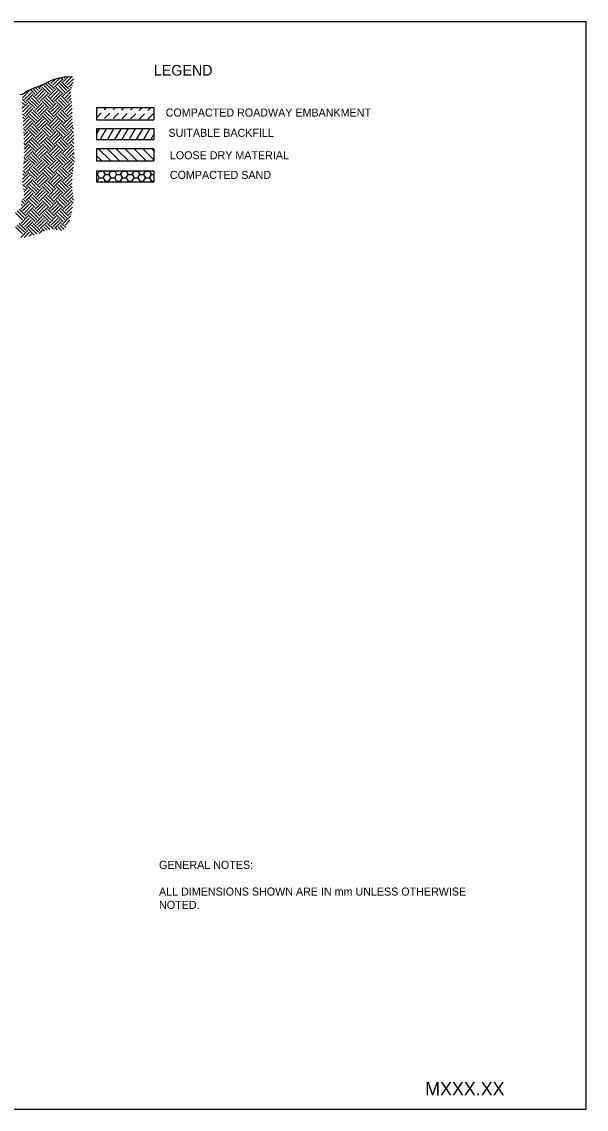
# Model space of a CAD drawing. Extents: x -439.1 to -407.9, y -458.1 to -436.2.
# Drawn here: x -418.43 to -407.86, y -458.05 to -437.68 of the extents above; entities that cross this region are included whole.
import ezdxf

# ---------------------------------------------------------------- set-up
doc = ezdxf.new("R2010")
doc.units = 0
for name, color, linetype in [('Bridge-Named Boundary', 7, 'Continuous'), ('Level 4', 7, 'Continuous'), ('Level 46', 7, 'Continuous')]:
    doc.layers.add(name, color=color, linetype=linetype)

msp = doc.modelspace()

# ---------------------------------------------------------------- linework, layer by layer
at = {"layer": 'Bridge-Named Boundary'}
msp.add_lwpolyline([(-439.109, -458.051), (-407.859, -458.051), (-407.859, -437.676), (-439.109, -437.676)], close=True, dxfattribs=at)
at = {"layer": 'Level 4'}
for p, q in [((-418.083, -438.901), (-418.035, -438.853)), ((-417.884, -439), (-418.016, -438.867)), ((-417.851, -438.967), (-417.983, -438.834)), ((-417.818, -438.934), (-417.94, -438.811)), ((-417.884, -438.834), (-417.805, -438.756)), ((-417.851, -438.867), (-417.718, -438.735)), ((-417.818, -438.901), (-417.685, -438.768)), ((-417.619, -439), (-417.751, -438.867)), ((-417.586, -438.967), (-417.718, -438.834)), ((-417.652, -438.768), (-417.688, -438.732)), ((-417.552, -438.934), (-417.685, -438.801)), ((-417.652, -438.801), (-417.559, -438.708)), ((-417.619, -438.735), (-417.627, -438.727)), ((-417.619, -438.834), (-417.493, -438.709)), ((-417.586, -438.867), (-417.462, -438.744)), ((-417.552, -438.901), (-417.469, -438.817)), ((-417.484, -438.87), (-417.486, -438.867)), ((-418.414, -439.099), (-418.282, -438.967)), ((-418.381, -439.133), (-418.248, -439)), ((-418.348, -439.166), (-418.215, -439.033)), ((-418.182, -439.033), (-418.269, -438.947)), ((-418.149, -439), (-418.222, -438.927)), ((-418.083, -439.199), (-418.215, -439.066)), ((-418.182, -439.066), (-418.05, -438.934)), ((-418.116, -438.967), (-418.172, -438.911)), ((-418.149, -439.099), (-418.016, -438.967)), ((-418.083, -438.934), (-418.124, -438.892)), ((-418.116, -439.133), (-417.983, -439)), ((-418.083, -439.166), (-417.95, -439.033)), ((-417.917, -439.033), (-418.05, -438.901)), ((-417.818, -439.199), (-417.95, -439.066)), ((-417.917, -439.066), (-417.784, -438.934)), ((-417.884, -439.099), (-417.751, -438.967)), ((-417.851, -439.133), (-417.718, -439)), ((-417.818, -439.166), (-417.685, -439.033)), ((-417.652, -439.033), (-417.784, -438.901)), ((-417.552, -439.199), (-417.685, -439.066)), ((-417.652, -439.066), (-417.519, -438.934)), ((-417.619, -439.099), (-417.509, -438.99)), ((-417.586, -439.133), (-417.511, -439.058)), ((-417.498, -438.922), (-417.519, -438.901)), ((-418.381, -439.232), (-418.423, -439.19)), ((-418.414, -439.265), (-418.423, -439.257)), ((-418.42, -439.304), (-418.315, -439.199)), ((-418.348, -439.199), (-418.419, -439.128)), ((-418.414, -439.365), (-418.282, -439.232)), ((-418.381, -439.398), (-418.248, -439.265)), ((-418.182, -439.298), (-418.315, -439.166)), ((-418.149, -439.265), (-418.282, -439.133)), ((-418.116, -439.232), (-418.248, -439.099)), ((-418.182, -439.332), (-418.05, -439.199)), ((-418.149, -439.365), (-418.016, -439.232)), ((-418.116, -439.398), (-417.983, -439.265)), ((-417.917, -439.298), (-418.05, -439.166)), ((-417.884, -439.265), (-418.016, -439.133)), ((-417.851, -439.232), (-417.983, -439.099)), ((-417.917, -439.332), (-417.784, -439.199)), ((-417.884, -439.365), (-417.751, -439.232)), ((-417.851, -439.398), (-417.718, -439.265)), ((-417.652, -439.298), (-417.784, -439.166)), ((-417.619, -439.265), (-417.751, -439.133)), ((-417.586, -439.232), (-417.718, -439.099)), ((-417.652, -439.332), (-417.519, -439.199)), ((-417.619, -439.365), (-417.491, -439.237)), ((-417.552, -439.166), (-417.503, -439.116)), ((-417.494, -439.191), (-417.519, -439.166)), ((-417.032, -439.283), (-415.957, -439.283)), ((-417.032, -439.283), (-417.032, -439.515)), ((-417.032, -439.308), (-417.007, -439.283)), ((-416.883, -439.325), (-416.841, -439.283)), ((-416.72, -439.328), (-416.676, -439.283)), ((-416.558, -439.332), (-416.51, -439.283)), ((-416.396, -439.335), (-416.344, -439.283)), ((-416.233, -439.338), (-416.178, -439.283)), ((-416.071, -439.341), (-416.013, -439.283)), ((-415.957, -439.283), (-415.957, -439.515)), ((-418.348, -439.464), (-418.414, -439.398)), ((-418.381, -439.497), (-418.409, -439.469)), ((-418.404, -439.553), (-418.315, -439.464)), ((-418.348, -439.431), (-418.215, -439.298)), ((-418.182, -439.564), (-418.315, -439.431)), ((-418.149, -439.53), (-418.282, -439.398)), ((-418.116, -439.497), (-418.248, -439.365)), ((-418.083, -439.464), (-418.215, -439.332)), ((-418.182, -439.597), (-418.05, -439.464)), ((-418.083, -439.431), (-417.95, -439.298)), ((-417.917, -439.564), (-418.05, -439.431)), ((-417.884, -439.53), (-418.016, -439.398)), ((-417.851, -439.497), (-417.983, -439.365)), ((-417.818, -439.464), (-417.95, -439.332)), ((-417.917, -439.597), (-417.784, -439.464)), ((-417.818, -439.431), (-417.685, -439.298)), ((-417.652, -439.564), (-417.784, -439.431)), ((-417.619, -439.53), (-417.751, -439.398)), ((-417.586, -439.497), (-417.718, -439.365)), ((-417.552, -439.464), (-417.685, -439.332)), ((-417.652, -439.597), (-417.519, -439.464)), ((-417.586, -439.398), (-417.489, -439.301)), ((-417.552, -439.431), (-417.488, -439.367)), ((-417.485, -439.466), (-417.519, -439.431)), ((-417.032, -439.474), (-416.943, -439.385)), ((-416.88, -439.487), (-416.78, -439.388)), ((-416.717, -439.491), (-416.618, -439.391)), ((-416.555, -439.494), (-416.455, -439.394)), ((-416.392, -439.497), (-416.293, -439.398)), ((-416.23, -439.501), (-416.13, -439.401)), ((-416.067, -439.504), (-415.968, -439.404)), ((-418.401, -439.617), (-418.282, -439.497)), ((-418.348, -439.729), (-418.399, -439.678)), ((-418.381, -439.663), (-418.248, -439.53)), ((-418.348, -439.696), (-418.215, -439.564)), ((-418.149, -439.796), (-418.282, -439.663)), ((-418.116, -439.762), (-418.248, -439.63)), ((-418.083, -439.729), (-418.215, -439.597)), ((-418.149, -439.63), (-418.016, -439.497)), ((-418.116, -439.663), (-417.983, -439.53)), ((-418.083, -439.696), (-417.95, -439.564)), ((-417.884, -439.796), (-418.016, -439.663)), ((-417.851, -439.762), (-417.983, -439.63)), ((-417.818, -439.729), (-417.95, -439.597)), ((-417.884, -439.63), (-417.751, -439.497)), ((-417.851, -439.663), (-417.718, -439.53)), ((-417.818, -439.696), (-417.685, -439.564)), ((-417.619, -439.796), (-417.751, -439.663)), ((-417.586, -439.762), (-417.718, -439.63)), ((-417.552, -439.729), (-417.685, -439.597)), ((-417.619, -439.63), (-417.486, -439.497)), ((-417.586, -439.663), (-417.477, -439.555)), ((-417.552, -439.696), (-417.471, -439.615)), ((-417.464, -439.685), (-417.486, -439.663)), ((-417.032, -439.515), (-415.957, -439.515)), ((-417.032, -439.674), (-415.957, -439.674)), ((-417.032, -439.674), (-417.032, -439.882)), ((-416.977, -439.674), (-417.032, -439.768)), ((-416.842, -439.674), (-416.962, -439.881)), ((-416.707, -439.674), (-416.826, -439.881)), ((-416.571, -439.674), (-416.691, -439.881)), ((-416.436, -439.674), (-416.556, -439.881)), ((-416.301, -439.674), (-416.42, -439.881)), ((-416.165, -439.674), (-416.285, -439.881)), ((-416.03, -439.674), (-416.15, -439.881)), ((-415.957, -439.674), (-415.957, -439.882)), ((-418.381, -439.762), (-418.397, -439.747)), ((-418.394, -439.809), (-418.315, -439.729)), ((-418.392, -439.873), (-418.282, -439.762)), ((-418.381, -439.928), (-418.248, -439.796)), ((-418.348, -439.961), (-418.215, -439.829)), ((-418.182, -439.829), (-418.315, -439.696)), ((-418.116, -440.028), (-418.248, -439.895)), ((-418.083, -439.994), (-418.215, -439.862)), ((-418.182, -439.862), (-418.05, -439.729)), ((-418.149, -439.895), (-418.016, -439.762)), ((-418.116, -439.928), (-417.983, -439.796)), ((-418.083, -439.961), (-417.95, -439.829)), ((-417.917, -439.829), (-418.05, -439.696)), ((-417.851, -440.028), (-417.983, -439.895)), ((-417.818, -439.994), (-417.95, -439.862)), ((-417.917, -439.862), (-417.784, -439.729)), ((-417.884, -439.895), (-417.751, -439.762)), ((-417.851, -439.928), (-417.718, -439.796)), ((-417.818, -439.961), (-417.685, -439.829)), ((-417.652, -439.829), (-417.784, -439.696)), ((-417.586, -440.028), (-417.718, -439.895)), ((-417.552, -439.994), (-417.685, -439.862)), ((-417.652, -439.862), (-417.519, -439.729)), ((-417.619, -439.895), (-417.486, -439.762)), ((-417.586, -439.928), (-417.456, -439.798)), ((-417.552, -439.961), (-417.455, -439.863)), ((-417.458, -439.757), (-417.519, -439.696)), ((-417.032, -439.882), (-415.957, -439.882)), ((-415.958, -439.783), (-416.015, -439.881)), ((-418.348, -439.994), (-418.389, -439.954)), ((-418.381, -440.028), (-418.386, -440.022)), ((-418.385, -440.064), (-418.315, -439.994)), ((-418.383, -440.129), (-418.282, -440.028)), ((-418.381, -440.193), (-418.248, -440.061)), ((-418.348, -440.226), (-418.215, -440.094)), ((-418.182, -440.094), (-418.315, -439.961)), ((-418.149, -440.061), (-418.282, -439.928)), ((-418.182, -440.127), (-418.05, -439.994)), ((-418.149, -440.16), (-418.016, -440.028)), ((-418.116, -440.193), (-417.983, -440.061)), ((-418.083, -440.226), (-417.95, -440.094)), ((-417.917, -440.094), (-418.05, -439.961)), ((-417.884, -440.061), (-418.016, -439.928)), ((-417.917, -440.127), (-417.784, -439.994)), ((-417.884, -440.16), (-417.751, -440.028)), ((-417.851, -440.193), (-417.718, -440.061)), ((-417.818, -440.226), (-417.685, -440.094)), ((-417.652, -440.094), (-417.784, -439.961)), ((-417.619, -440.061), (-417.751, -439.928)), ((-417.652, -440.127), (-417.519, -439.994)), ((-417.619, -440.16), (-417.486, -440.028)), ((-417.586, -440.193), (-417.453, -440.061)), ((-417.455, -440.026), (-417.519, -439.961)), ((-417.455, -439.959), (-417.486, -439.928)), ((-417.032, -440.053), (-415.957, -440.053)), ((-417.032, -440.053), (-417.032, -440.284)), ((-416.997, -440.052), (-416.765, -440.284)), ((-416.832, -440.052), (-416.6, -440.284)), ((-416.666, -440.052), (-416.434, -440.284)), ((-416.5, -440.052), (-416.268, -440.284)), ((-416.334, -440.052), (-416.102, -440.284)), ((-416.169, -440.052), (-415.958, -440.263)), ((-416.003, -440.052), (-415.958, -440.098)), ((-415.957, -440.053), (-415.957, -440.284)), ((-418.399, -440.41), (-418.282, -440.293)), ((-418.395, -440.34), (-418.315, -440.26)), ((-418.381, -440.293), (-418.392, -440.282)), ((-418.348, -440.26), (-418.388, -440.22)), ((-418.182, -440.359), (-418.315, -440.226)), ((-418.149, -440.326), (-418.282, -440.193)), ((-418.116, -440.293), (-418.248, -440.16)), ((-418.083, -440.26), (-418.215, -440.127)), ((-418.182, -440.392), (-418.05, -440.26)), ((-418.149, -440.425), (-418.016, -440.293)), ((-417.917, -440.359), (-418.05, -440.226)), ((-417.884, -440.326), (-418.016, -440.193)), ((-417.851, -440.293), (-417.983, -440.16)), ((-417.818, -440.26), (-417.95, -440.127)), ((-417.917, -440.392), (-417.784, -440.26)), ((-417.884, -440.425), (-417.751, -440.293)), ((-417.652, -440.359), (-417.784, -440.226)), ((-417.619, -440.326), (-417.751, -440.193)), ((-417.586, -440.293), (-417.718, -440.16)), ((-417.552, -440.26), (-417.685, -440.127)), ((-417.652, -440.392), (-417.519, -440.26)), ((-417.619, -440.425), (-417.486, -440.293)), ((-417.552, -440.226), (-417.45, -440.124)), ((-417.445, -440.3), (-417.519, -440.226)), ((-417.444, -440.236), (-417.486, -440.193)), ((-417.447, -440.166), (-417.453, -440.16)), ((-417.032, -440.184), (-416.931, -440.284)), ((-417.032, -440.284), (-415.957, -440.284)), ((-418.348, -440.525), (-418.402, -440.47)), ((-418.381, -440.458), (-418.248, -440.326)), ((-418.348, -440.492), (-418.215, -440.359)), ((-418.182, -440.624), (-418.315, -440.492)), ((-418.149, -440.591), (-418.282, -440.458)), ((-418.116, -440.558), (-418.248, -440.425)), ((-418.083, -440.525), (-418.215, -440.392)), ((-418.116, -440.458), (-417.983, -440.326)), ((-418.083, -440.492), (-417.95, -440.359)), ((-417.917, -440.624), (-418.05, -440.492)), ((-417.884, -440.591), (-418.016, -440.458)), ((-417.851, -440.558), (-417.983, -440.425)), ((-417.818, -440.525), (-417.95, -440.392)), ((-417.851, -440.458), (-417.718, -440.326)), ((-417.818, -440.492), (-417.685, -440.359)), ((-417.652, -440.624), (-417.784, -440.492)), ((-417.619, -440.591), (-417.751, -440.458)), ((-417.586, -440.558), (-417.718, -440.425)), ((-417.552, -440.525), (-417.685, -440.392)), ((-417.586, -440.458), (-417.453, -440.326)), ((-417.552, -440.492), (-417.459, -440.399)), ((-417.478, -440.533), (-417.519, -440.492)), ((-417.47, -440.474), (-417.486, -440.458)), ((-417.032, -440.468), (-417.032, -440.675)), ((-417.032, -440.468), (-415.957, -440.468)), ((-417.014, -440.54), (-416.978, -440.478)), ((-416.984, -440.467), (-416.978, -440.478)), ((-416.978, -440.478), (-416.905, -440.478)), ((-416.905, -440.478), (-416.899, -440.467)), ((-416.905, -440.478), (-416.869, -440.54)), ((-416.797, -440.54), (-416.761, -440.478)), ((-416.767, -440.467), (-416.761, -440.478)), ((-416.761, -440.478), (-416.689, -440.478)), ((-416.689, -440.478), (-416.683, -440.467)), ((-416.689, -440.478), (-416.653, -440.54)), ((-416.581, -440.54), (-416.545, -440.478)), ((-416.551, -440.467), (-416.545, -440.478)), ((-416.545, -440.478), (-416.472, -440.478)), ((-416.472, -440.478), (-416.466, -440.467)), ((-416.472, -440.478), (-416.436, -440.54)), ((-416.364, -440.54), (-416.328, -440.478)), ((-416.334, -440.467), (-416.328, -440.478)), ((-416.328, -440.478), (-416.256, -440.478)), ((-416.256, -440.478), (-416.25, -440.467)), ((-416.256, -440.478), (-416.22, -440.54)), ((-416.148, -440.54), (-416.112, -440.478)), ((-416.118, -440.467), (-416.112, -440.478)), ((-416.112, -440.478), (-416.039, -440.478)), ((-416.039, -440.478), (-416.033, -440.467)), ((-416.039, -440.478), (-416.003, -440.54)), ((-415.957, -440.468), (-415.957, -440.675)), ((-418.415, -440.625), (-418.315, -440.525)), ((-418.414, -440.69), (-418.282, -440.558)), ((-418.381, -440.558), (-418.408, -440.531)), ((-418.381, -440.724), (-418.248, -440.591)), ((-418.348, -440.757), (-418.215, -440.624)), ((-418.116, -440.823), (-418.248, -440.69)), ((-418.083, -440.79), (-418.215, -440.657)), ((-418.182, -440.657), (-418.05, -440.525)), ((-418.149, -440.69), (-418.016, -440.558)), ((-418.116, -440.724), (-417.983, -440.591)), ((-418.083, -440.757), (-417.95, -440.624)), ((-417.851, -440.823), (-417.983, -440.69)), ((-417.818, -440.79), (-417.95, -440.657)), ((-417.917, -440.657), (-417.784, -440.525)), ((-417.884, -440.69), (-417.751, -440.558)), ((-417.851, -440.724), (-417.718, -440.591)), ((-417.818, -440.757), (-417.685, -440.624)), ((-417.586, -440.823), (-417.718, -440.69)), ((-417.552, -440.79), (-417.685, -440.657)), ((-417.652, -440.657), (-417.519, -440.525)), ((-417.619, -440.69), (-417.486, -440.558)), ((-417.586, -440.724), (-417.489, -440.627)), ((-417.552, -440.757), (-417.493, -440.698)), ((-417.032, -440.54), (-417.014, -440.54)), ((-417.032, -440.665), (-417.014, -440.665)), ((-417.032, -440.675), (-415.957, -440.675)), ((-417.014, -440.54), (-416.978, -440.603)), ((-417.014, -440.665), (-416.978, -440.603)), ((-417.014, -440.665), (-417.008, -440.675)), ((-416.978, -440.603), (-416.905, -440.603)), ((-416.905, -440.603), (-416.869, -440.54)), ((-416.905, -440.603), (-416.869, -440.665)), ((-416.875, -440.675), (-416.869, -440.665)), ((-416.869, -440.54), (-416.797, -440.54)), ((-416.869, -440.665), (-416.797, -440.665)), ((-416.797, -440.54), (-416.761, -440.603)), ((-416.797, -440.665), (-416.761, -440.603)), ((-416.797, -440.665), (-416.792, -440.675)), ((-416.761, -440.603), (-416.689, -440.603)), ((-416.689, -440.603), (-416.653, -440.54)), ((-416.689, -440.603), (-416.653, -440.665)), ((-416.658, -440.675), (-416.653, -440.665)), ((-416.653, -440.54), (-416.581, -440.54)), ((-416.653, -440.665), (-416.581, -440.665)), ((-416.581, -440.54), (-416.545, -440.603)), ((-416.581, -440.665), (-416.545, -440.603)), ((-416.581, -440.665), (-416.575, -440.675)), ((-416.545, -440.603), (-416.472, -440.603)), ((-416.472, -440.603), (-416.436, -440.54)), ((-416.472, -440.603), (-416.436, -440.665)), ((-416.442, -440.675), (-416.436, -440.665)), ((-416.436, -440.54), (-416.364, -440.54)), ((-416.436, -440.665), (-416.364, -440.665)), ((-416.364, -440.54), (-416.328, -440.603)), ((-416.364, -440.665), (-416.328, -440.603)), ((-416.364, -440.665), (-416.359, -440.675)), ((-416.328, -440.603), (-416.256, -440.603)), ((-416.256, -440.603), (-416.22, -440.54)), ((-416.256, -440.603), (-416.22, -440.665)), ((-416.225, -440.675), (-416.22, -440.665)), ((-416.22, -440.54), (-416.148, -440.54)), ((-416.22, -440.665), (-416.148, -440.665)), ((-416.148, -440.54), (-416.112, -440.603)), ((-416.148, -440.665), (-416.112, -440.603)), ((-416.148, -440.665), (-416.142, -440.675)), ((-416.112, -440.603), (-416.039, -440.603)), ((-416.039, -440.603), (-416.003, -440.54)), ((-416.039, -440.603), (-416.003, -440.665)), ((-416.009, -440.675), (-416.003, -440.665)), ((-416.003, -440.54), (-415.958, -440.54)), ((-416.003, -440.665), (-415.958, -440.665)), ((-418.348, -440.79), (-418.414, -440.724)), ((-418.381, -440.823), (-418.4, -440.804)), ((-418.393, -440.934), (-418.282, -440.823)), ((-418.391, -440.867), (-418.315, -440.79)), ((-418.381, -440.989), (-418.248, -440.856)), ((-418.348, -441.022), (-418.215, -440.889)), ((-418.182, -440.889), (-418.315, -440.757)), ((-418.149, -440.856), (-418.282, -440.724)), ((-418.182, -440.923), (-418.05, -440.79)), ((-418.149, -440.956), (-418.016, -440.823)), ((-418.116, -440.989), (-417.983, -440.856)), ((-418.083, -441.022), (-417.95, -440.889)), ((-417.917, -440.889), (-418.05, -440.757)), ((-417.884, -440.856), (-418.016, -440.724)), ((-417.917, -440.923), (-417.784, -440.79)), ((-417.884, -440.956), (-417.751, -440.823)), ((-417.851, -440.989), (-417.718, -440.856)), ((-417.818, -441.022), (-417.685, -440.889)), ((-417.652, -440.889), (-417.784, -440.757)), ((-417.619, -440.856), (-417.751, -440.724)), ((-417.652, -440.923), (-417.519, -440.79)), ((-417.619, -440.956), (-417.487, -440.824)), ((-417.586, -440.989), (-417.476, -440.879)), ((-417.489, -440.787), (-417.519, -440.757)), ((-418.447, -441.188), (-418.315, -441.055)), ((-418.414, -441.121), (-418.442, -441.093)), ((-418.381, -441.088), (-418.437, -441.033)), ((-418.414, -441.221), (-418.282, -441.088)), ((-418.348, -441.055), (-418.41, -440.993)), ((-418.182, -441.155), (-418.315, -441.022)), ((-418.149, -441.121), (-418.282, -440.989)), ((-418.116, -441.088), (-418.248, -440.956)), ((-418.083, -441.055), (-418.215, -440.923)), ((-418.182, -441.188), (-418.05, -441.055)), ((-418.149, -441.221), (-418.016, -441.088)), ((-417.917, -441.155), (-418.05, -441.022)), ((-417.884, -441.121), (-418.016, -440.989)), ((-417.851, -441.088), (-417.983, -440.956)), ((-417.818, -441.055), (-417.95, -440.923)), ((-417.917, -441.188), (-417.784, -441.055)), ((-417.884, -441.221), (-417.751, -441.088)), ((-417.652, -441.155), (-417.784, -441.022)), ((-417.619, -441.121), (-417.751, -440.989)), ((-417.586, -441.088), (-417.718, -440.956)), ((-417.552, -441.055), (-417.685, -440.923)), ((-417.652, -441.188), (-417.519, -441.055)), ((-417.619, -441.221), (-417.486, -441.088)), ((-417.552, -441.022), (-417.465, -440.935)), ((-417.466, -441.075), (-417.519, -441.022)), ((-417.455, -441.02), (-417.486, -440.989)), ((-418.414, -441.387), (-418.547, -441.254)), ((-418.381, -441.353), (-418.514, -441.221)), ((-418.348, -441.32), (-418.48, -441.188)), ((-418.447, -441.453), (-418.315, -441.32)), ((-418.381, -441.254), (-418.248, -441.121)), ((-418.348, -441.287), (-418.215, -441.155)), ((-418.182, -441.42), (-418.315, -441.287)), ((-418.149, -441.387), (-418.282, -441.254)), ((-418.116, -441.353), (-418.248, -441.221)), ((-418.083, -441.32), (-418.215, -441.188)), ((-418.182, -441.453), (-418.05, -441.32)), ((-418.116, -441.254), (-417.983, -441.121)), ((-418.083, -441.287), (-417.95, -441.155)), ((-417.917, -441.42), (-418.05, -441.287)), ((-417.884, -441.387), (-418.016, -441.254)), ((-417.851, -441.353), (-417.983, -441.221)), ((-417.818, -441.32), (-417.95, -441.188)), ((-417.917, -441.453), (-417.784, -441.32)), ((-417.851, -441.254), (-417.718, -441.121)), ((-417.818, -441.287), (-417.685, -441.155)), ((-417.652, -441.42), (-417.784, -441.287)), ((-417.619, -441.387), (-417.751, -441.254)), ((-417.586, -441.353), (-417.718, -441.221)), ((-417.552, -441.32), (-417.685, -441.188)), ((-417.652, -441.453), (-417.519, -441.32)), ((-417.586, -441.254), (-417.479, -441.148)), ((-417.552, -441.287), (-417.493, -441.228)), ((-417.505, -441.302), (-417.519, -441.287)), ((-418.414, -441.652), (-418.547, -441.519)), ((-418.381, -441.619), (-418.514, -441.486)), ((-418.348, -441.585), (-418.48, -441.453)), ((-418.414, -441.486), (-418.282, -441.353)), ((-418.381, -441.519), (-418.248, -441.387)), ((-418.348, -441.552), (-418.215, -441.42)), ((-418.149, -441.652), (-418.282, -441.519)), ((-418.116, -441.619), (-418.248, -441.486)), ((-418.083, -441.585), (-418.215, -441.453)), ((-418.149, -441.486), (-418.016, -441.353)), ((-418.116, -441.519), (-417.983, -441.387)), ((-418.083, -441.552), (-417.95, -441.42)), ((-417.953, -441.583), (-418.016, -441.519)), ((-417.902, -441.568), (-417.983, -441.486)), ((-417.838, -441.565), (-417.95, -441.453)), ((-417.884, -441.486), (-417.751, -441.353)), ((-417.851, -441.519), (-417.718, -441.387)), ((-417.818, -441.552), (-417.685, -441.42)), ((-417.685, -441.586), (-417.751, -441.519)), ((-417.635, -441.569), (-417.718, -441.486)), ((-417.605, -441.533), (-417.685, -441.453)), ((-417.619, -441.486), (-417.527, -441.395)), ((-418.447, -441.718), (-418.315, -441.585)), ((-418.382, -441.719), (-418.282, -441.619)), ((-418.195, -441.672), (-418.315, -441.552)), ((-418.298, -441.701), (-418.248, -441.652)), ((-418.107, -441.643), (-418.05, -441.585)), ((-418.003, -441.599), (-418.05, -441.552)), ((-417.765, -441.572), (-417.784, -441.552))]:
    msp.add_line(p, q, dxfattribs=at)
msp.add_lwpolyline([(-417.481, -438.705), (-417.634, -438.714), (-417.782, -438.746), (-417.872, -438.779), (-417.959, -438.819), (-418.051, -438.863), (-418.146, -438.902), (-418.248, -438.936), (-418.343, -438.985), (-418.379, -439.014), (-418.416, -439.037), (-418.457, -439.044)], dxfattribs=at)

# ---------------------------------------------------------------- texts
for s, height, p in [('LEGEND', 0.2, (-415.957, -438.685)), ('COMPACTED ROADWAY EMBANKMENT', 0.15, (-415.735, -439.452)), ('SUITABLE BACKFILL', 0.15, (-415.682, -439.832)), ('LOOSE DRY MATERIAL', 0.15, (-415.656, -440.252)), ('COMPACTED SAND', 0.15, (-415.656, -440.62))]:
    msp.add_text(s, height=height, dxfattribs=at).set_placement(p)
at = {"layer": 'Level 46'}
for s, height, p in [('GENERAL NOTES:', 0.15, (-415.859, -453.547)), ('ALL DIMENSIONS SHOWN ARE IN mm UNLESS OTHERWISE ', 0.15, (-415.859, -454.047)), ('NOTED.', 0.15, (-415.859, -454.297)), ('MXXX.XX', 0.25, (-410.875, -457.792))]:
    msp.add_text(s, height=height, dxfattribs=at).set_placement(p)

doc.saveas('drawing.dxf')
